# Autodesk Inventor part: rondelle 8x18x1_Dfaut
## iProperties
Created: 2006-03
Part Number: rondelle 8x18x1_Dfaut
Document SubType Name: Modeling
Designer: Flavien MARTY
Author: Flavien MARTY
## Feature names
1. Base1
